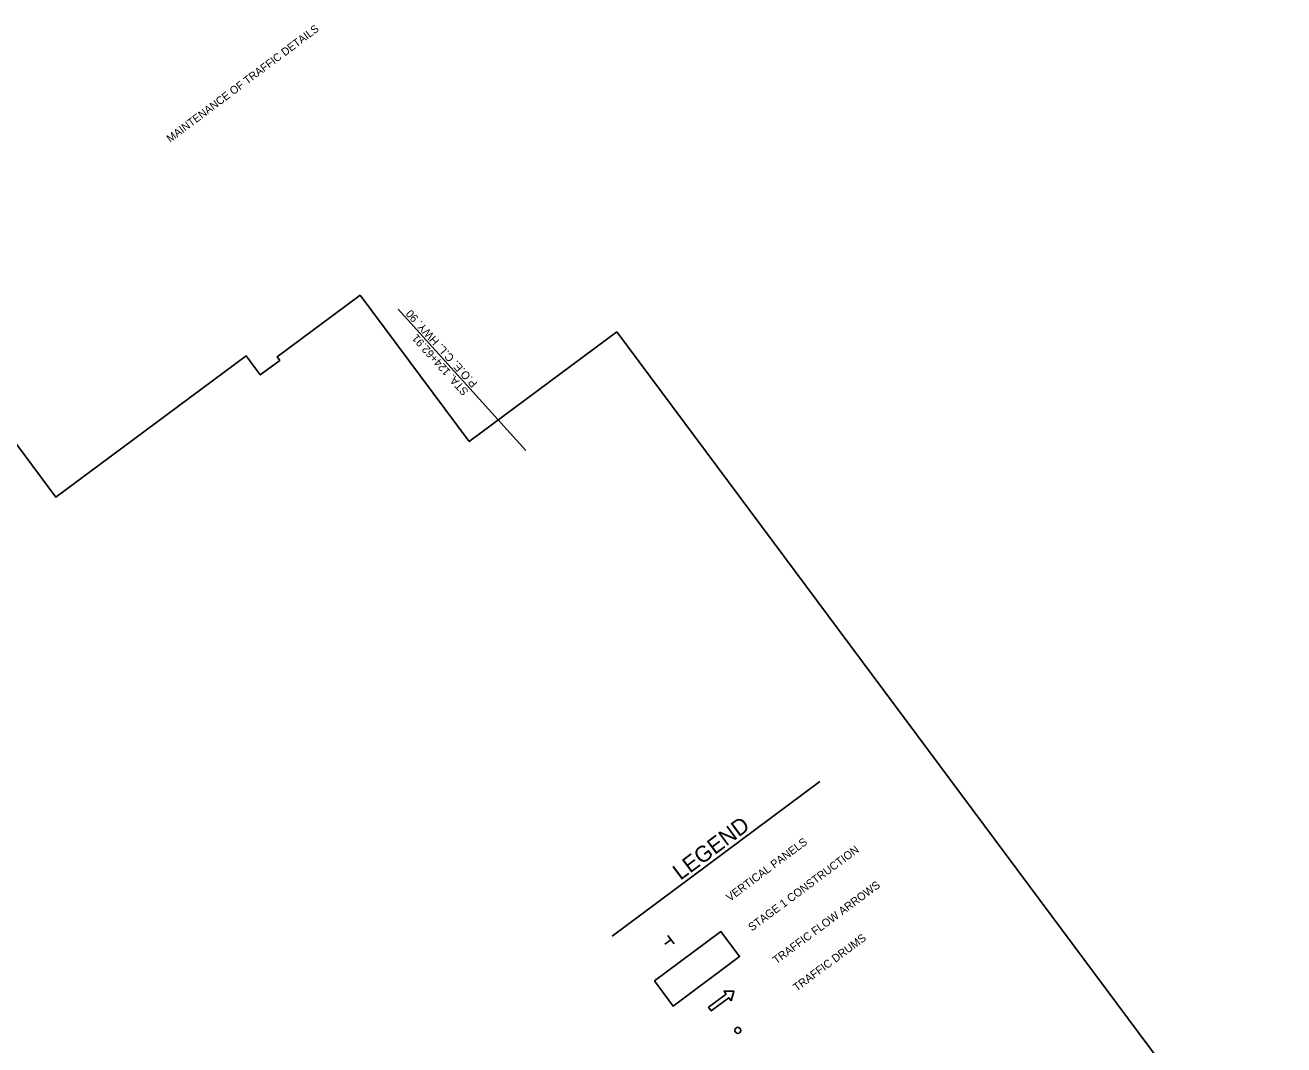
# Model space of a CAD drawing. Extents: x 1571137 to 1573037, y 731477 to 733451.
# Drawn here: x 1572093 to 1573037, y 732687 to 733451 of the extents above; entities that cross this region are included whole.
import ezdxf

# ---------------------------------------------------------------- set-up
doc = ezdxf.new("R2010")
doc.units = 0
for name, color, linetype in [('Level 47', 7, 'Continuous'), ('R_Annotation', 7, 'Continuous'), ('R_Border', 7, 'Continuous'), ('R_Horz Alg Annot', 7, 'Continuous'), ('R_MOT', 7, 'Continuous')]:
    doc.layers.add(name, color=color, linetype=linetype)

msp = doc.modelspace()

# ---------------------------------------------------------------- linework, layer by layer
at = {"layer": 'Level 47'}
msp.add_circle((1572627.46, 732697.82), 2.25, dxfattribs=at)
at = {"layer": 'R_Annotation'}
msp.add_line((1572533.27, 732768.54), (1572688.84, 732884.32), dxfattribs=at)
at = {"layer": 'R_Horz Alg Annot'}
msp.add_line((1572468.45, 733132.61), (1572372.81, 733238.55), dxfattribs=at)
for points in [[(1572536.74, 733221.56), (1573036.71, 732549.76), (1571756.88, 731597.29), (1571136.98, 732430.24), (1572086.85, 733137.16), (1572116.34, 733097.53), (1572258.81, 733203.56), (1572269.47, 733189.25), (1572284.07, 733200.11), (1572282.13, 733202.72), (1572344.44, 733249.09)], [(1572344.44, 733249.09), (1572426.17, 733139.27), (1572536.74, 733221.56)]]:
    msp.add_lwpolyline(points, dxfattribs=at)
at = {"layer": 'R_MOT'}
for p, q in [((1572577.17, 732765.8), (1572572.78, 732762.54)), ((1572574.88, 732769.06), (1572579.66, 732762.64))]:
    msp.add_line(p, q, dxfattribs=at)
for points in [[(1572564.93, 732734.86), (1572614.73, 732771.92), (1572628.75, 732753.08), (1572578.95, 732716.02)], [(1572622.48, 732720.05), (1572624.48, 732727.14), (1572617.11, 732727.27), (1572618.79, 732725.01), (1572605.51, 732715.13), (1572607.53, 732712.42), (1572620.8, 732722.3)]]:
    msp.add_lwpolyline(points, close=True, dxfattribs=at)

# ---------------------------------------------------------------- texts
at = {"layer": 'R_Annotation'}
for s, height, rotation, p in [('LEGEND', 12, 36.65759, (1572584.4, 732809.94)), ('VERTICAL PANELS', 6, 36.65758, (1572621.47, 732794.19)), ('STAGE 1 CONSTRUCTION', 6, 36.65758, (1572638.06, 732771.9)), ('TRAFFIC FLOW ARROWS', 6, 36.65758, (1572656.41, 732747.24)), ('TRAFFIC DRUMS', 6, 36.65758, (1572671.65, 732726.76))]:
    msp.add_text(s, height=height, rotation=rotation, dxfattribs=at).set_placement(p)
at = {"layer": 'R_Border'}
msp.add_text('MAINTENANCE OF TRAFFIC DETAILS', height=5.862, rotation=36.96355, dxfattribs=at).set_placement((1572201.97, 733363.22))
at = {"layer": 'R_Horz Alg Annot'}
for s, p in [('P.O.E. C.L. HWY. 90', (1572432.71, 733183.04)), ('STA. 124+62.91', (1572426.03, 733177.01))]:
    msp.add_text(s, height=6, rotation=132.07494, dxfattribs=at).set_placement(p)

doc.saveas('drawing.dxf')
